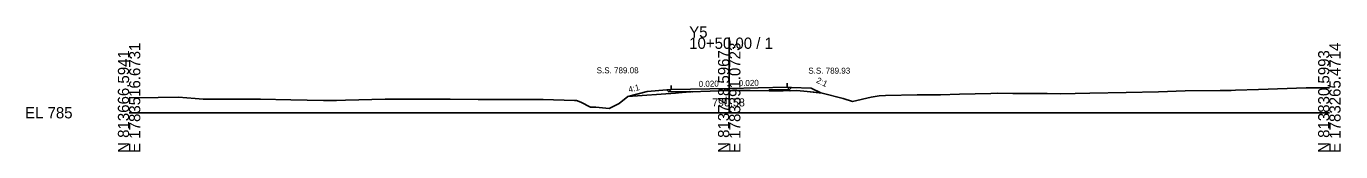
# Model space of a CAD drawing. Extents: x -26 to 1603, y -10 to 6526.
# Drawn here: x -25.7 to 302.8, y 990.3 to 1021.5 of the extents above; entities that cross this region are included whole.
import ezdxf

# ---------------------------------------------------------------- set-up
doc = ezdxf.new("R2010")
doc.units = 0
for name, color, linetype in [('Exist Cross Section Cell', 7, 'Continuous'), ('Exist XS Center Line Elevation Label', 7, 'Continuous'), ('Exist XS Ground Line', 7, 'Continuous'), ('Prop XS Dump Level', 7, 'Continuous'), ('Prop XS Earthwork Shape', 7, 'Continuous'), ('Prop XS EOT Tick Mark', 7, 'Continuous'), ('Prop XS Finish Grade', 7, 'Continuous'), ('Prop XS Finish Grade Earthwork', 7, 'Continuous'), ('Prop XS Finish Grade Pavement', 7, 'Continuous'), ('Prop XS Pvmt Edge Slope', 7, 'Continuous'), ('Prop XS SE Text', 7, 'Continuous'), ('Prop XS Side Slope Text', 7, 'Continuous'), ('Prop XS SS Elevation Text', 7, 'Continuous'), ('Prop XS Subgrade Earthwork', 7, 'Continuous')]:
    doc.layers.add(name, color=color, linetype=linetype)

msp = doc.modelspace()

# ---------------------------------------------------------------- linework, layer by layer
at = {"layer": 'Exist Cross Section Cell'}
for p, q in [((150, 1000), (150, 1018.74)), ((0, 1000), (150, 1000)), ((150, 1000), (300, 1000))]:
    msp.add_line(p, q, dxfattribs=at)
at = {"layer": 'Exist XS Ground Line'}
for p, q in [((140.49, 1005.23), (150, 1005.58)), ((150, 1005.58), (150, 1005.58)), ((150, 1005.58), (155.23, 1005.54)), ((155.23, 1005.54), (160.25, 1005.46)), ((160.25, 1005.46), (163.51, 1005.51)), ((163.51, 1005.51), (166.86, 1005.55)), ((166.86, 1005.55), (169.45, 1005.27)), ((257.27, 1005.2), (263.96, 1005.43)), ((263.96, 1005.43), (272.7, 1005.56)), ((272.7, 1005.56), (275.45, 1005.58)), ((275.45, 1005.58), (276.52, 1005.61)), ((276.52, 1005.61), (282.25, 1005.81)), ((282.25, 1005.81), (294.17, 1006.2)), ((294.17, 1006.2), (300, 1006.25)), ((0, 1003.78), (2.2, 1003.74)), ((2.2, 1003.74), (12.38, 1003.85)), ((12.38, 1003.85), (16.54, 1003.55)), ((16.54, 1003.55), (18.49, 1003.35)), ((18.49, 1003.35), (27.42, 1003.39)), ((27.42, 1003.39), (32.81, 1003.41)), ((32.81, 1003.41), (40.45, 1003.2)), ((40.45, 1003.2), (48.62, 1003.07)), ((48.62, 1003.07), (51.86, 1003.05)), ((51.86, 1003.05), (54.11, 1003.16)), ((54.11, 1003.16), (63.97, 1003.36)), ((63.97, 1003.36), (77.39, 1003.38)), ((77.39, 1003.38), (79.36, 1003.37)), ((79.36, 1003.37), (80.25, 1003.39)), ((80.25, 1003.39), (87.25, 1003.29)), ((87.25, 1003.29), (103.53, 1003.32)), ((103.53, 1003.32), (111.32, 1003.1)), ((111.32, 1003.1), (111.85, 1003.1)), ((111.85, 1003.1), (112.91, 1002.68)), ((112.91, 1002.68), (115.34, 1001.4)), ((119.99, 1001.1), (122.49, 1002.32)), ((122.49, 1002.32), (124.68, 1004.08)), ((124.68, 1004.08), (136.59, 1004.88)), ((136.59, 1004.88), (137.32, 1004.94)), ((137.32, 1004.94), (140.14, 1005.21)), ((140.14, 1005.21), (140.49, 1005.23)), ((169.45, 1005.27), (173.26, 1004.9)), ((173.26, 1004.9), (178.5, 1003.54)), ((178.5, 1003.54), (180.83, 1002.85)), ((180.83, 1002.85), (185.51, 1003.87)), ((185.51, 1003.87), (187.52, 1004.26)), ((187.52, 1004.26), (189.04, 1004.27)), ((189.04, 1004.27), (196.98, 1004.43)), ((196.98, 1004.43), (201.36, 1004.49)), ((201.36, 1004.49), (202.78, 1004.5)), ((202.78, 1004.5), (207.58, 1004.65)), ((207.58, 1004.65), (215.41, 1004.83)), ((215.41, 1004.83), (216.97, 1004.85)), ((216.97, 1004.85), (220.9, 1004.84)), ((220.9, 1004.84), (229.48, 1004.8)), ((229.48, 1004.8), (232.78, 1004.76)), ((232.78, 1004.76), (240.16, 1004.89)), ((240.16, 1004.89), (249.24, 1005.04)), ((249.24, 1005.04), (257.27, 1005.2)), ((115.34, 1001.4), (116.64, 1001.38)), ((116.64, 1001.38), (119.99, 1001.1))]:
    msp.add_line(p, q, dxfattribs=at)
at = {"layer": 'Prop XS Dump Level'}
for p, q in [((135.5, 1005.79), (150, 1006.08)), ((150, 1006.08), (164.5, 1006.37))]:
    msp.add_line(p, q, dxfattribs=at)
at = {"layer": 'Prop XS Earthwork Shape'}
for points in [[(137.32, 1004.94), (140.14, 1005.21), (140.14, 1005.3), (134.9, 1005.2), (134.4, 1005.7), (129.5, 1005.31), (124.68, 1004.08), (136.59, 1004.88)], [(160, 1005.46), (160.25, 1005.46), (163.51, 1005.51), (166.86, 1005.55), (169.45, 1005.27), (172.9, 1004.93), (170.5, 1006.13), (165.6, 1006.33), (165.07, 1005.8), (160, 1005.7)]]:
    msp.add_lwpolyline(points, close=True, dxfattribs=at)
at = {"layer": 'Prop XS EOT Tick Mark'}
for p, q in [((135.5, 1005.79), (135.5, 1006.79)), ((135.5, 1005.79), (135.5, 1006.79)), ((164.5, 1006.37), (164.5, 1007.37))]:
    msp.add_line(p, q, dxfattribs=at)
at = {"layer": 'Prop XS Finish Grade'}
for p, q in [((135.5, 1005.79), (134.4, 1005.7)), ((164.5, 1006.37), (165.6, 1006.33))]:
    msp.add_line(p, q, dxfattribs=at)
at = {"layer": 'Prop XS Finish Grade Earthwork'}
for p, q in [((129.5, 1005.31), (124.68, 1004.08)), ((134.4, 1005.7), (129.5, 1005.31)), ((165.6, 1006.33), (170.5, 1006.13)), ((170.5, 1006.13), (172.9, 1004.93))]:
    msp.add_line(p, q, dxfattribs=at)
at = {"layer": 'Prop XS Finish Grade Pavement'}
for p, q in [((135.5, 1005.79), (150, 1006.08)), ((150, 1006.08), (164.5, 1006.37))]:
    msp.add_line(p, q, dxfattribs=at)
at = {"layer": 'Prop XS Pvmt Edge Slope'}
for p, q in [((135.5, 1005.79), (134.9, 1005.2)), ((164.5, 1006.37), (165.07, 1005.8))]:
    msp.add_line(p, q, dxfattribs=at)
at = {"layer": 'Prop XS Subgrade Earthwork'}
for p, q in [((134.9, 1005.2), (134.4, 1005.7)), ((160, 1005.7), (165.07, 1005.8)), ((160, 1005.7), (160, 1005.46)), ((165.07, 1005.8), (165.6, 1006.33)), ((134.9, 1005.2), (140.14, 1005.3)), ((140.14, 1005.3), (140.14, 1005.21))]:
    msp.add_line(p, q, dxfattribs=at)

# ---------------------------------------------------------------- texts
at = {"layer": 'Exist Cross Section Cell'}
for s, p in [('Y5', (140, 1018.74)), ('10+50.00 / 1', (140, 1015.94)), ('EL 785', (-26, 998.6))]:
    msp.add_text(s, height=2.8, dxfattribs=at).set_placement(p)
for s, p in [('N 813666.5941', (0, 990)), ('E 1783516.6731', (2.8, 990)), ('N 813748.5967', (150, 990)), ('E 1783391.0723', (152.8, 990)), ('N 813830.5993', (300, 990)), ('E 1783265.4714', (302.8, 990))]:
    msp.add_text(s, height=2.8, rotation=90, dxfattribs=at).set_placement(p)
at = {"layer": 'Exist XS Center Line Elevation Label'}
msp.add_text('790.58', height=2, dxfattribs=at).set_placement((145.73, 1001.58))
at = {"layer": 'Prop XS Dump Level'}
for s, height, p in [('Case1', 0.04, (129.5, 1005.27)), ('Eop', 0.3, (164.74, 1005.25)), ('Case1', 0.04, (170.5, 1006.09)), ('Eop', 0.3, (140.14, 1004.91))]:
    msp.add_text(s, height=height, dxfattribs=at).set_placement(p)
at = {"layer": 'Prop XS SE Text'}
for p in [(142.38, 1006.43), (152.38, 1006.63)]:
    msp.add_text('0.020', height=1.5, rotation=1.1458, dxfattribs=at).set_placement(p)
at = {"layer": 'Prop XS Side Slope Text'}
for s, rotation, p in [('2:1', 335.255, (171.61, 1007.56)), ('4:1', 14.0362, (125, 1005.02))]:
    msp.add_text(s, height=1.5, rotation=rotation, dxfattribs=at).set_placement(p)
at = {"layer": 'Prop XS SS Elevation Text'}
for s, p in [('S.S. 789.08', (116.87, 1009.83)), ('S.S. 789.93', (169.77, 1009.75))]:
    msp.add_text(s, height=1.5, dxfattribs=at).set_placement(p)

doc.saveas('drawing.dxf')
